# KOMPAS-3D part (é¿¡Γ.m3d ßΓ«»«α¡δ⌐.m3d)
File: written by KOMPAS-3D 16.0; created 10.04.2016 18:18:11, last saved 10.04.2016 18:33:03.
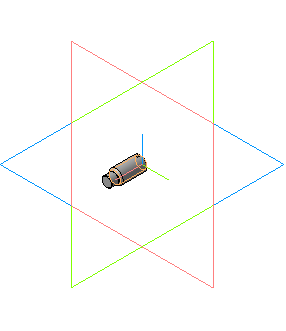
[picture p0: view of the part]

Referenced files in E:\Libs\PartLib\DATA\vault\Methods\Kompas\3D\: PLib_Screw_GOST_1478-84_900.m3d
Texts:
  Винт А.М5-6gx12 ГОСТ 1478-93
  (-) Винт А.М5-6gx12 ГОСТ 1478-93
